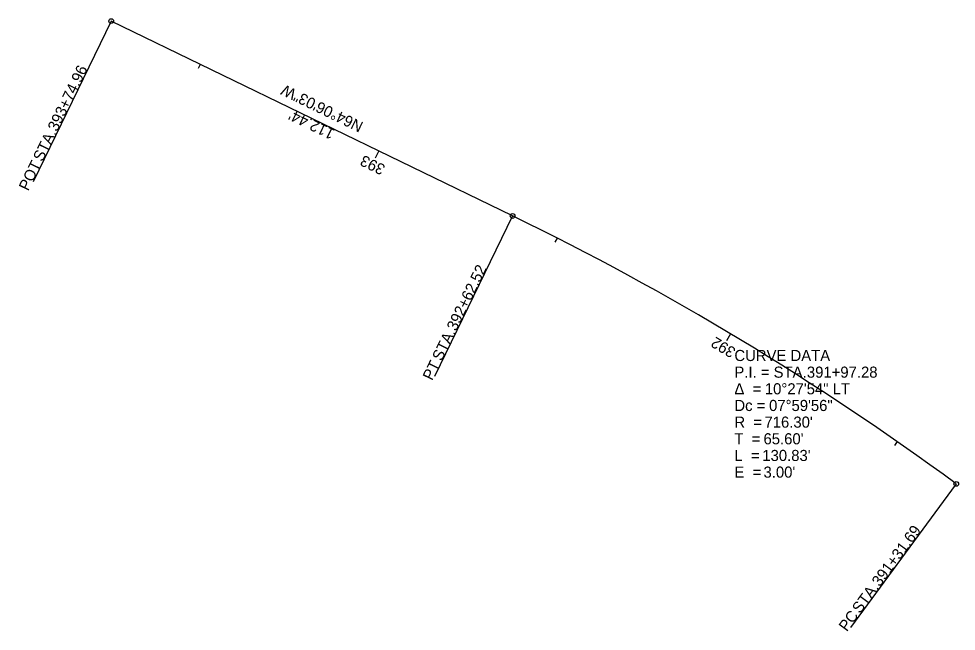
# Model space of a CAD drawing. Extents: x 111442 to 112326, y 429427 to 431077.
# Drawn here: x 111442.3 to 111678.6, y 430922.6 to 431077 of the extents above; entities that cross this region are included whole.
import ezdxf

# ---------------------------------------------------------------- set-up
doc = ezdxf.new("R2010")
doc.units = 0
for name, color, linetype in [('GE_P_Alignment', 7, 'Continuous'), ('GE_P_Alignment_100_Bearings', 7, 'Continuous'), ('GE_P_Alignment_100_Cardinal_Points', 7, 'Continuous'), ('GE_P_Alignment_100_Curve_Data', 7, 'Continuous'), ('GE_P_Alignment_100_Distances', 7, 'Continuous'), ('GE_P_Alignment_100_Stations', 7, 'Continuous')]:
    doc.layers.add(name, color=color, linetype=linetype)

msp = doc.modelspace()

# ---------------------------------------------------------------- linework, layer by layer
at = {"layer": 'GE_P_Alignment'}
msp.add_line((111566.74, 431027.32), (111465.59, 431076.44), dxfattribs=at)
msp.add_arc((111253.84, 430382.98), 716.3, 53.63414, 64.09904, dxfattribs=at)
at = {"layer": 'GE_P_Alignment_100_Cardinal_Points'}
for p, q in [((111465.59, 431076.44), (111445.93, 431035.96)), ((111566.74, 431027.32), (111547.08, 430986.84)), ((111678.57, 430959.77), (111651.88, 430923.54))]:
    msp.add_line(p, q, dxfattribs=at)
for centre in [(111465.59, 431076.44), (111566.74, 431027.32), (111678.57, 430959.77)]:
    msp.add_circle(centre, 0.6, dxfattribs=at)
at = {"layer": 'GE_P_Alignment_100_Stations'}
for p, q in [((111488.04, 431065.54), (111487.51, 431064.46)), ((111533.02, 431043.7), (111532.14, 431041.9)), ((111577.95, 431021.76), (111577.4, 431020.69)), ((111621.71, 430997.6), (111620.68, 430995.88)), ((111663.68, 430970.44), (111662.99, 430969.46))]:
    msp.add_line(p, q, dxfattribs=at)

# ---------------------------------------------------------------- texts
at = {"layer": 'GE_P_Alignment_100_Bearings'}
msp.add_text('N64°06\'03"W', height=2.8, rotation=154.1008, dxfattribs=at).set_placement((111529.34, 431050.82))
at = {"layer": 'GE_P_Alignment_100_Cardinal_Points'}
for s, rotation, p in [('393+74.96', 64.1008, (111451.94, 431048.43)), (' STA. ', 64.1008, (111447.81, 431039.92)), ('POT', 64.1008, (111444.67, 431033.45)), ('392+62.52', 64.1008, (111552.51, 430998.13)), (' STA. ', 64.1008, (111548.39, 430989.63)), ('PT', 64.1008, (111546.46, 430985.66)), ('391+31.69', 53.6341, (111659.3, 430933.69)), (' STA. ', 53.6341, (111653.7, 430926.08)), ('PC', 53.6341, (111650.98, 430922.38))]:
    msp.add_text(s, height=2.8, rotation=rotation, dxfattribs=at).set_placement(p)
at = {"layer": 'GE_P_Alignment_100_Curve_Data'}
for s, p in [('CURVE DATA', (111622.65, 430990.75)), ('P.I. = STA. ', (111622.65, 430986.55)), ('391+97.28', (111640.92, 430986.55)), ('Δ  = ', (111622.65, 430982.35)), ('10°27\'54" LT', (111630.33, 430982.35)), ('Dc = ', (111622.65, 430978.15)), ('07°59\'56"', (111631.39, 430978.15)), ('R  = ', (111622.65, 430973.95)), ("716.30'", (111630.23, 430973.95)), ('T  = ', (111622.65, 430969.75)), ("65.60'", (111629.99, 430969.75)), ('L  = ', (111622.65, 430965.55)), ("130.83'", (111629.69, 430965.55)), ('E  = ', (111622.65, 430961.35)), ("3.00'", (111629.99, 430961.35))]:
    msp.add_text(s, height=2.8, dxfattribs=at).set_placement(p)
at = {"layer": 'GE_P_Alignment_100_Distances'}
msp.add_text("112.44'", height=2.8, rotation=154.1008, dxfattribs=at).set_placement((111522.16, 431048.95))
at = {"layer": 'GE_P_Alignment_100_Stations'}
for s, rotation, p in [('393', 154.1008, (111534.87, 431040.02)), ('392', 149.0985, (111623.24, 430993.77))]:
    msp.add_text(s, height=2.8, rotation=rotation, dxfattribs=at).set_placement(p)

doc.saveas('drawing.dxf')
